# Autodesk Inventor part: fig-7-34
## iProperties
Shininess: 77.0
Length Units: 11269
Angle Units: 11279
Time Units: 11290
Mass Units: 11283
Length Display Precision: 3
Angle Display Precision: 2
Created: 2002-01
Part Number: fig-7-34
Document SubType Name: Modeling
Designer: CADSoft
Density: 0.0
Volumn: 0.0
Area: 0.0
PropertySet Name: Model Information
Control State: 0
Master: False
Checked Out: False
Author: CADSoft
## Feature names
1. Coil5
